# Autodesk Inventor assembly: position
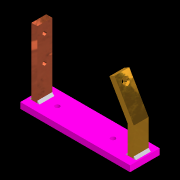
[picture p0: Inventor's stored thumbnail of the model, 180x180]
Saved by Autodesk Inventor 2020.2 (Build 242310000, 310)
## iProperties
Manager: ASSEMBLY
Company: 24
Created: 2020-10
Part Number: position
Document SubType Name: Weldment
Designer: Apardo
Weld Material: Aluminum 6061, Welded
Project: PLATE ROLLING MACHINE
Cost Center: 1
Engineer: STEEL METAL
Stock Number: 3
Engr Approved By: D. JAEGER
Author: Apardo
Revision Number: 1.0
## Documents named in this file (4)
- C:\Users\Apardo\Documents\Proyectos\Dietrich\Proyecto 1\PLATE ROLLING MACHINE\position.iam
- C:\Users\Apardo\Documents\Proyectos\Dietrich\Proyecto 1\PLATE ROLLING MACHINE\position 1A.ipt
- C:\Users\Apardo\Documents\Proyectos\Dietrich\Proyecto 1\PLATE ROLLING MACHINE\position 1B.ipt
- C:\Users\Apardo\Documents\Proyectos\Dietrich\Proyecto 1\PLATE ROLLING MACHINE\position 1C.ipt
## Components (3 placed, 3 different names)
1. position 1A:1 — Mate:1, Flush:1, Flush:2, Mate:2, Flush:3
2. position 1B:1 — Mate:1, Flush:1, Flush:2, Flush:4
3. position 1C:1 — Mate:2, Flush:3, Flush:4
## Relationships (6: Flush 4, Mate 2)
- Mate:1: position 1A:1 ↔ position 1B:1
- Flush:1: position 1A:1 ↔ position 1B:1
- Flush:2: position 1A:1 ↔ position 1B:1
- Mate:2: position 1A:1 ↔ position 1C:1
- Flush:3: position 1A:1 ↔ position 1C:1
- Flush:4: position 1B:1 ↔ position 1C:1
